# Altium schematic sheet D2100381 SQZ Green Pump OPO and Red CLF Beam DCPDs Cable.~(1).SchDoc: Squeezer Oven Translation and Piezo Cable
size A; Organization: LIGO Laboratory; Address1: California Institute of Technology; Address2: Massachusetts Institute of Technology; DocumentNumber: D1700438; Revision: V2; SheetNumber: 1; SheetTotal: 1; Engineer: R.  Abbott
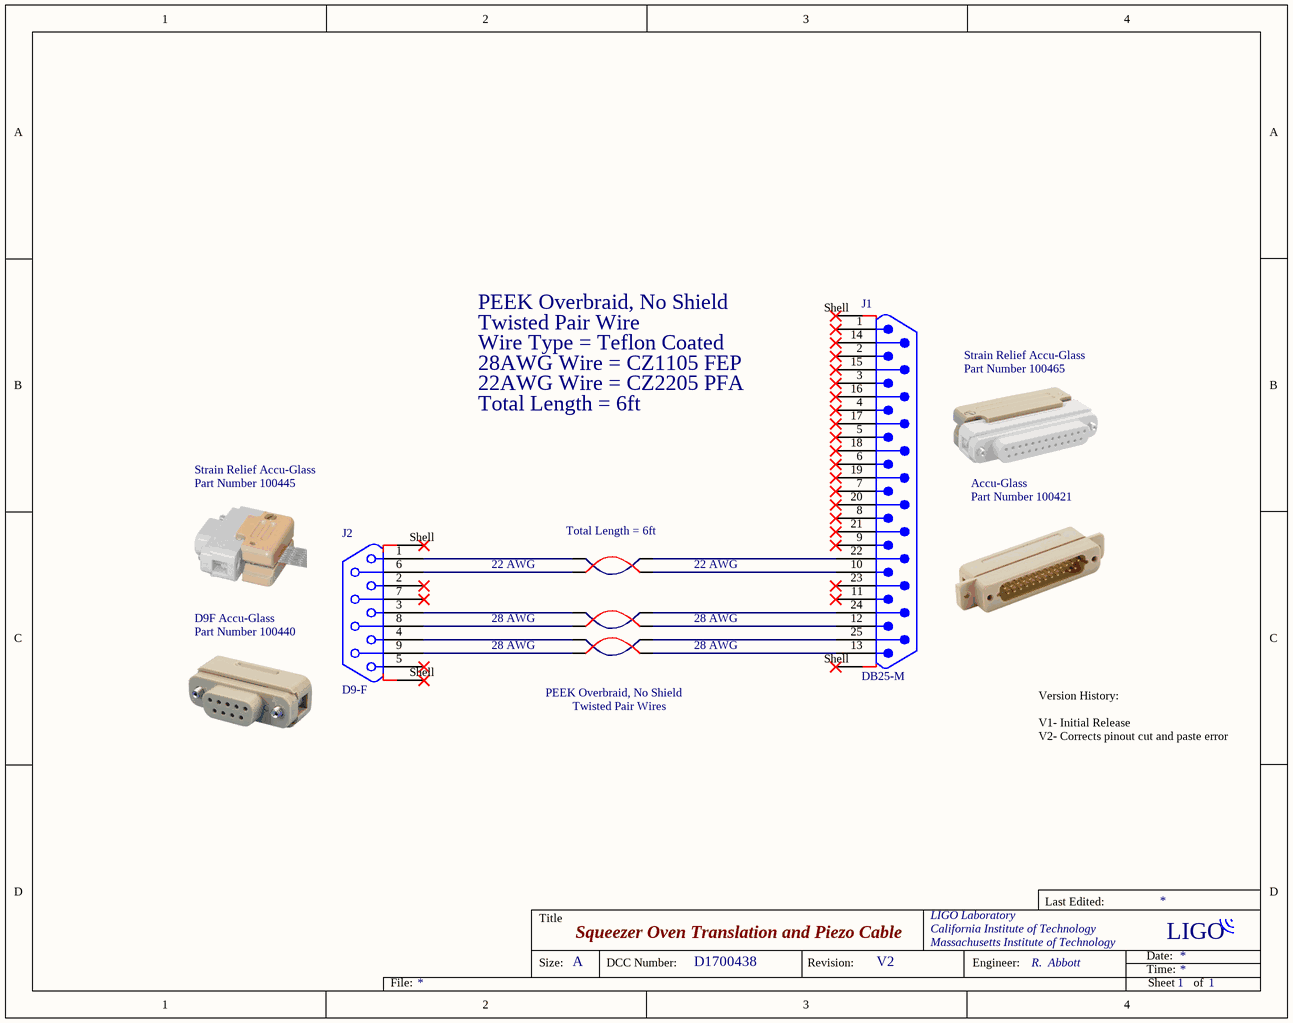
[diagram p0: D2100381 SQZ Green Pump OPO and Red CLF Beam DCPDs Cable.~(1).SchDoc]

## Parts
J1  DB25-M
J2  D9-F
TW1  Twisted Pair  (value not drawn)
TW2  Twisted Pair  (value not drawn)
TW3  Twisted Pair  (value not drawn)

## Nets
NetJ1_10: J1.10 TW1.2A
NetJ1_12: J1.12 TW2.2A
NetJ1_13: J1.13 TW3.2A
NetJ1_22: J1.22 TW1.1A
NetJ1_24: J1.24 TW2.1A
NetJ1_25: J1.25 TW3.1A
NetJ2_1: J2.1 TW1.1B
NetJ2_3: J2.3 TW2.1B
NetJ2_4: J2.4 TW3.1B
NetJ2_6: J2.6 TW1.2B
NetJ2_8: J2.8 TW2.2B
NetJ2_9: J2.9 TW3.2B

Not connected (* = marked no-connect by the designer): J1 1* 2* 3* 4* 5* 6* 7* 8* 9* 11* 14* 15* 16* 17* 18* 19* 20* 21* 23* Shell*; J2 2* 5* 7* Shell*

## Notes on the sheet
- PEEK Overbraid, No Shield
- Wire Type = Teflon Coated
- Twisted Pair Wire
- 28AWG Wire = CZ1105 FEP
- Strain Relief Accu-Glass
- Part Number 100465
- Total Length = 6ft
- 22AWG Wire = CZ2205 PFA
- Part Number 100445
- Accu-Glass
- Part Number 100421
- 22 AWG
- (near TW1) Total Length = 6ft
- D9F Accu-Glass
- Part Number 100440
- 28 AWG
- (near TW3) PEEK Overbraid, No Shield
- Twisted Pair Wires
- Version History:
  V1- Initial Release
  V2- Corrects pinout cut and paste error

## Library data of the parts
J1 = D25-M-Shell: 25 Pin Male Cable End, D-Sub with Backshell
J2 = D9-F-Shell: 9 Pin Female Cable End, D-Sub with Backshell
